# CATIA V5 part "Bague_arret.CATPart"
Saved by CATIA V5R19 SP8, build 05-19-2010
Part number: Bague_arret
Bounding box of the stored display mesh (mm): x -45 to 45, y -44.808 to 44.808, z -1 to 3
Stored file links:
  G:\EU_thinkMotion\CFAO_2010\MMS_groupe1\MMS_groupe1\OK\vduret\vduret\CATIA\Bague_arret.CATPart
  F:\CFAO_TP_fin\Machine_de_coupe_sans_geo.CATProduct
  G:\EU_thinkMotion\CFAO_2010\MMS_groupe1\MMS_groupe1\OK\vduret\vduret\CATIA\Disque_porteur.CATPart
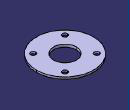
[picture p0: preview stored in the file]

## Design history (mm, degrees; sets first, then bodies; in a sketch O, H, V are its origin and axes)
Body1 (main body)
  Sketch1 on xy-plane, origin (0, 0, 0), H (1, 0, 0), V (0, 1, 0)
    circle A1 centre (0, 0) radius 45
    circle A2 centre (0, 0) radius 18
    circle A3 centre (-25, 25) radius 4
    point P1 (-25, 25)
    circle A4 centre (25, 25) radius 4
    circle A5 centre (25, -25) radius 4
    circle A6 centre (-25, -25) radius 4
    radius A1 = 45
    radius A2 = 18
    radius A3 = 4
    distance P1 H = 25
    distance P1 V = 25
    symmetry: A3 A4 V, A4 A5 H, A3 A6 H
  Pad1: profile Sketch1, direction (0, 0, 1), length 3
  Sketch2 on start face of Pad1, origin (0, 0, 0), H (1, 0, 0), V (0, -1, 0)
    circle A1 centre (0, 0) radius 20
    circle A2 centre (0, 0) radius 18
    reference projected circle E1 centre (0, 0) radius 18 from edge [face of Pad1 from Sketch1.A2 | start face of Pad1]
    radius A1 = 20
    coincidence: A2 E1
  Pad2: profile Sketch2, direction (0, 0, -1), length 1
